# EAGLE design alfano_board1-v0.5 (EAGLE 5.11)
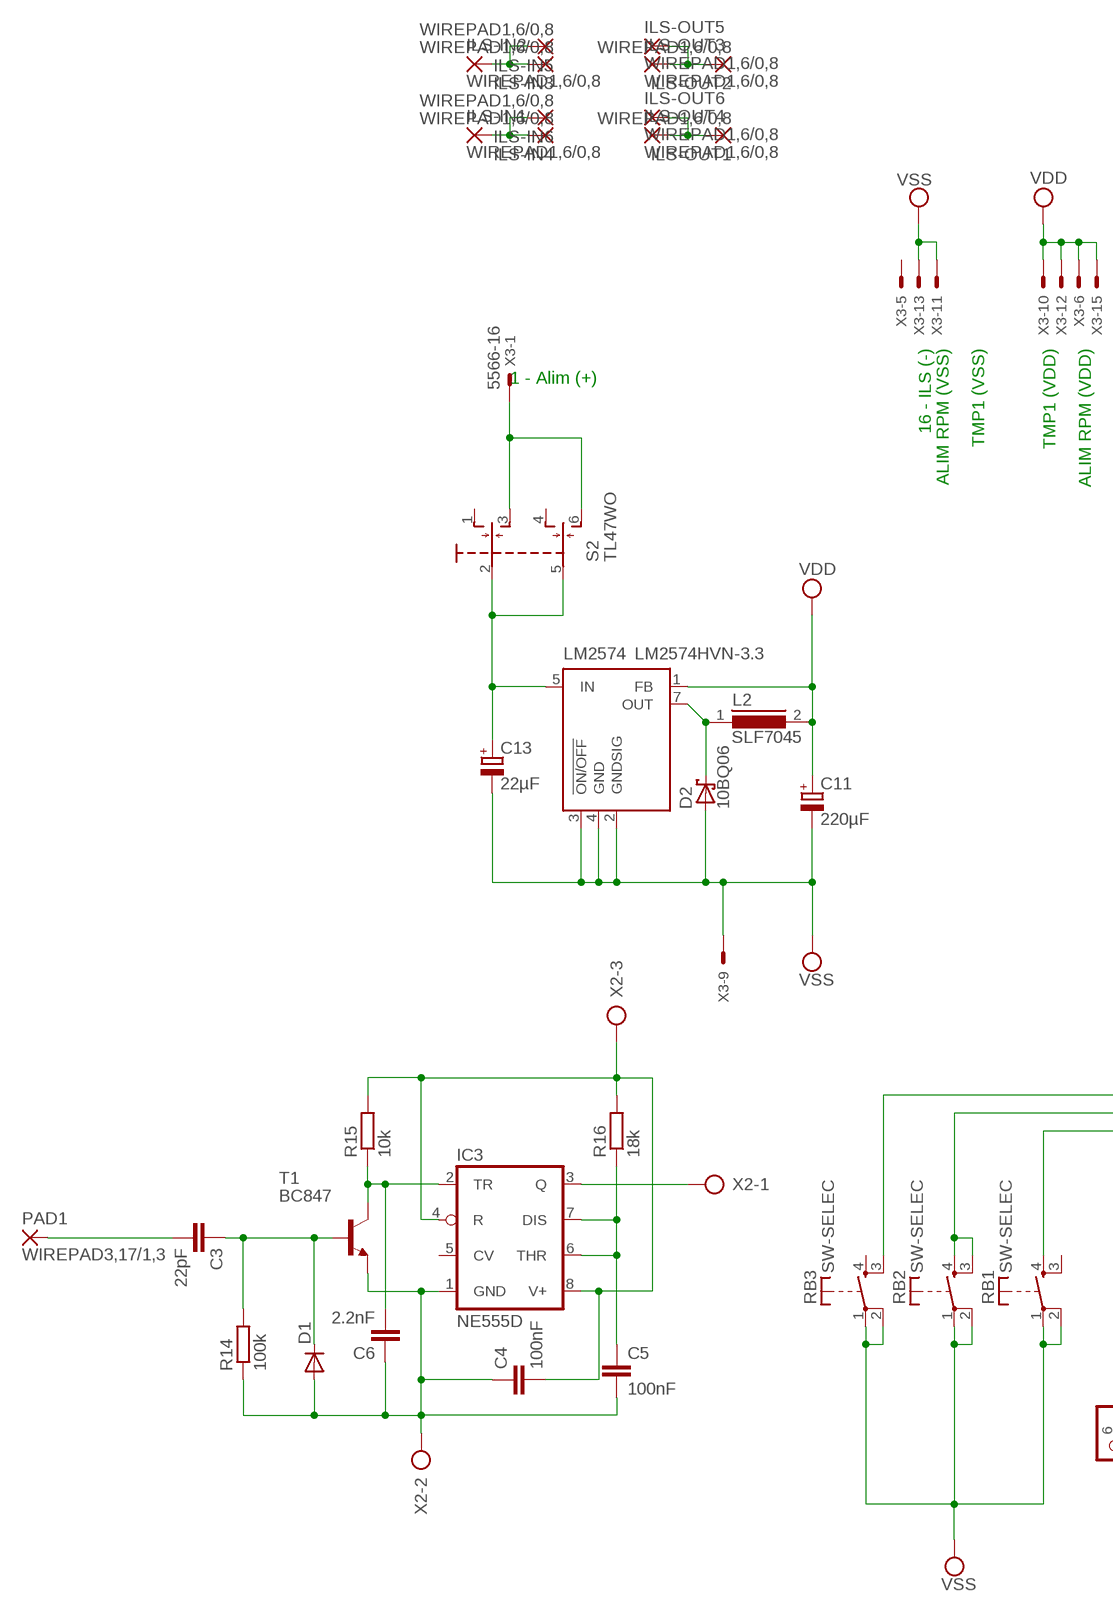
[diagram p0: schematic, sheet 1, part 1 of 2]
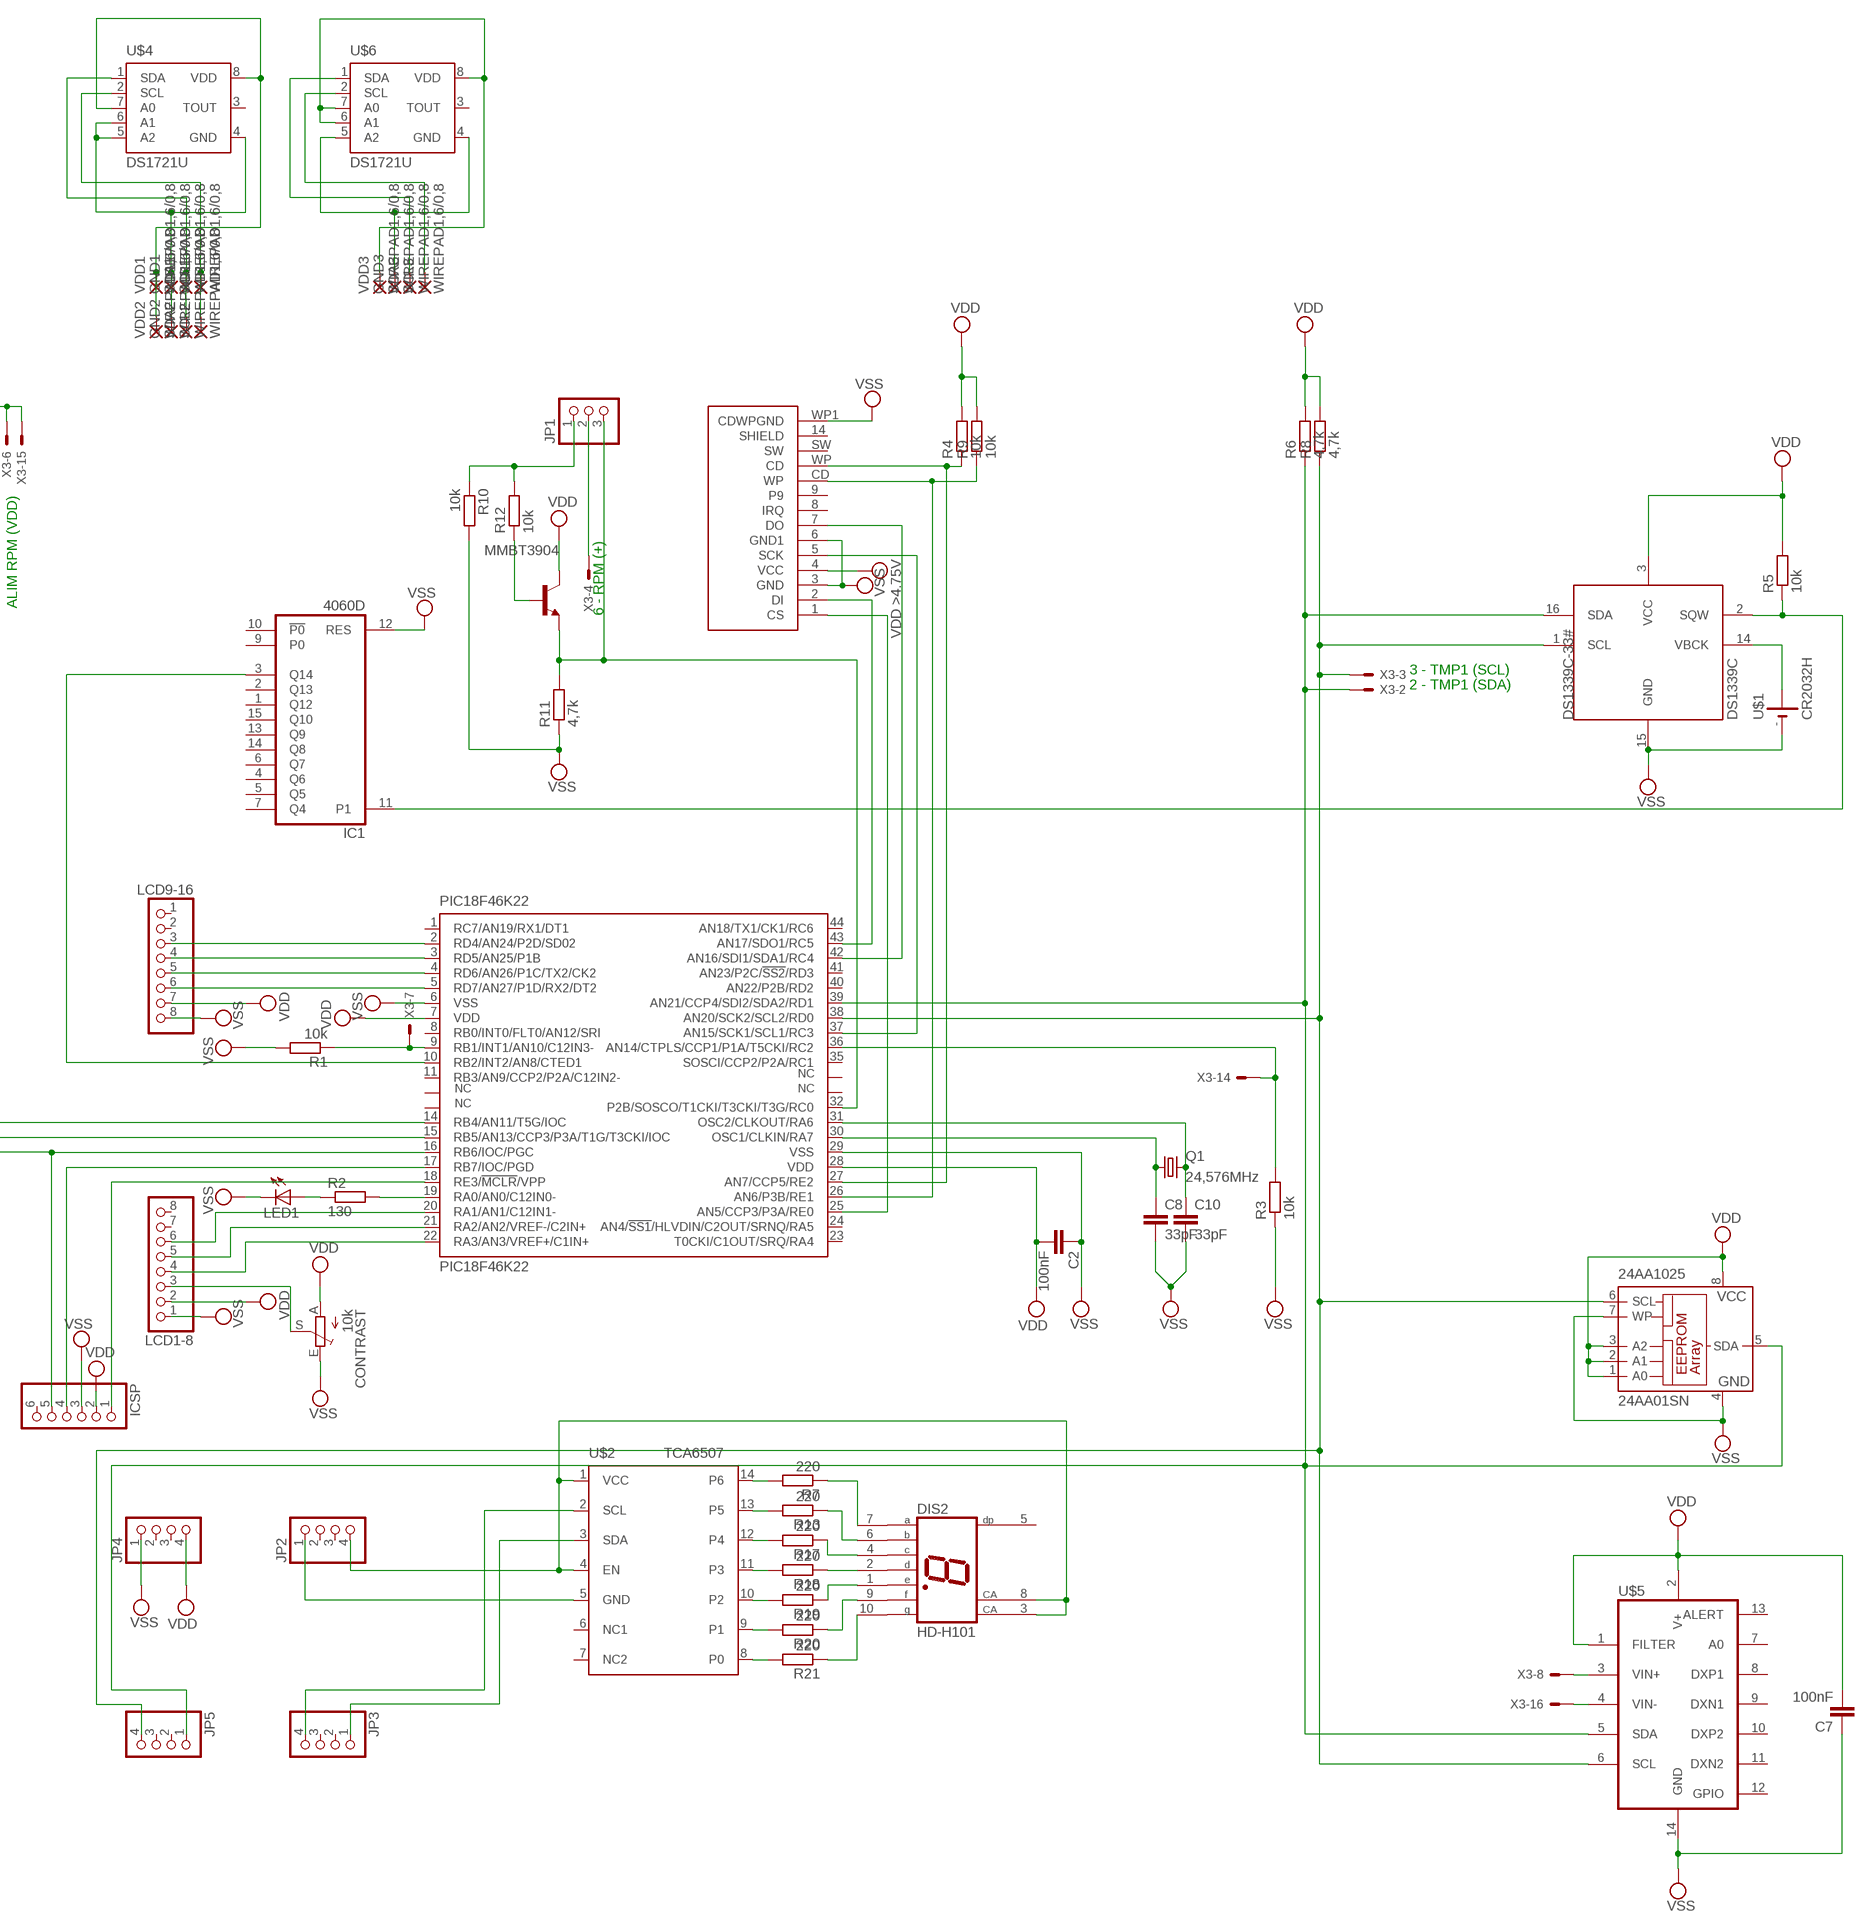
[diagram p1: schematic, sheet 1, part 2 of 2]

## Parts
24AA1025  24AA01SN  [SO-08]
C2  100nF  C-EUC1206  [C1206]
C3  22pF  C-EUC1206  [C1206]
C4  100nF  C-EUC1206  [C1206]
C5  100nF  C-EUC1206  [C1206]
C6  2.2nF  C-EUC1206  [C1206]
C7  100nF  C-EUC1206  [C1206]
C8  33pF  C-EUC1206  [C1206]
C10  33pF  C-EUC1206  [C1206]
C11  220µF  CPOL-EUUD-8X10  [UD-8X10_NICHICON]
C13  22µF  CPOL-EUUD-4X5,8  [UD-4X5,8_NICHICON]
CONTRAST  10k  TRIM_EU-B25P  [B25P]
D1  DIODE-MINIMELF  [MINIMELF]
D2  10BQ06  MBRS130LT3  [SMB]
DIS2  HD-H101  [HDSP-M]
DS1339C-33#  DS1339C  [DS1339C]
GND1  WIREPAD1,6/0,8  [1,6/0,8]
GND2  WIREPAD1,6/0,8  [1,6/0,8]
GND3  WIREPAD1,6/0,8  [1,6/0,8]
IC1  4060D  [SO16]
IC3  NE555D  [SO08]
ICSP  PINHD-1X6  [1X06]
ILS-IN1  WIREPAD1,6/0,8  [1,6/0,8]
ILS-IN2  WIREPAD1,6/0,8  [1,6/0,8]
ILS-IN3  WIREPAD1,6/0,8  [1,6/0,8]
ILS-IN4  WIREPAD1,6/0,8  [1,6/0,8]
ILS-IN5  WIREPAD1,6/0,8  [1,6/0,8]
ILS-IN6  WIREPAD1,6/0,8  [1,6/0,8]
ILS-OUT1  WIREPAD1,6/0,8  [1,6/0,8]
ILS-OUT2  WIREPAD1,6/0,8  [1,6/0,8]
ILS-OUT3  WIREPAD1,6/0,8  [1,6/0,8]
ILS-OUT4  WIREPAD1,6/0,8  [1,6/0,8]
ILS-OUT5  WIREPAD1,6/0,8  [1,6/0,8]
ILS-OUT6  WIREPAD1,6/0,8  [1,6/0,8]
JP1  PINHD-1X3  [1X03]
JP2  PINHD-1X4  [1X04]
JP3  PINHD-1X4  [1X04]
JP4  PINHD-1X4  [1X04]
JP5  PINHD-1X4  [1X04]
L2  SLF7045  [SLF7045]
LCD1-8  PINHD-1X8  [1X08]
LCD9-16  PINHD-1X8  [1X08]
LED1  LED5MM  [LED5MM]
LM2574  LM2574HVN-3.3  [DIL08]
MMBT3904  MMBT3904LT1-NPN-SOT23-BEC  [SOT23-BEC]
PAD1  WIREPAD3,17/1,3  [3,17/1,3]
PIC18F46K22  PIC18F46K22  [TQFP44]
Q1  24,576MHz  CRYSTALHC49U-V  [HC49U-V]
R1  10k  R-EU_M1206  [M1206]
R2  130  R-EU_M1206  [M1206]
R3  10k  R-EU_M1206  [M1206]
R4  10k  R-EU_M1206  [M1206]
R5  10k  R-EU_M1206  [M1206]
R6  4,7k  R-EU_M1206  [M1206]
R7  220  R-EU_M1206  [M1206]
R8  4,7k  R-EU_M1206  [M1206]
R9  10k  R-EU_M1206  [M1206]
R10  10k  R-EU_M1206  [M1206]
R11  4,7k  R-EU_M1206  [M1206]
R12  10k  R-EU_M1206  [M1206]
R13  220  R-EU_M1206  [M1206]
R14  100k  R-EU_M1206  [M1206]
R15  10k  R-EU_M1206  [M1206]
R16  18k  R-EU_M1206  [M1206]
R17  220  R-EU_M1206  [M1206]
R18  220  R-EU_M1206  [M1206]
R19  220  R-EU_M1206  [M1206]
R20  220  R-EU_M1206  [M1206]
R21  220  R-EU_M1206  [M1206]
RB1  SW-SELEC  [SW-SELEC]
RB2  SW-SELEC  [SW-SELEC]
RB3  SW-SELEC  [SW-SELEC]
S2  TL47WO  [TL4XWO]
SCL1  WIREPAD1,6/0,8  [1,6/0,8]
SCL2  WIREPAD1,6/0,8  [1,6/0,8]
SCL3  WIREPAD1,6/0,8  [1,6/0,8]
SDA1  WIREPAD1,6/0,8  [1,6/0,8]
SDA2  WIREPAD1,6/0,8  [1,6/0,8]
SDA3  WIREPAD1,6/0,8  [1,6/0,8]
T1  BC847  [SOT23]
U$1  CR2032H  [CR2032H]
U$2  TCA6507  [TCA6507]
U$3  SD_CARD_SOCKETSD  [SD-MMC_SOCKET-PP]
U$4  DS1721U  [UMAX-8PIN]
U$5  TMP512  [TMP512]
U$6  DS1721U  [UMAX-8PIN]
VDD1  WIREPAD1,6/0,8  [1,6/0,8]
VDD2  WIREPAD1,6/0,8  [1,6/0,8]
VDD3  WIREPAD1,6/0,8  [1,6/0,8]
X2  AK500/3  [AK500/3]
X3  5566-16  [5566-16]

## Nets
N$1: 24AA1025.6(SCL) DS1339C-33#.1(SCL) JP5.4 PIC18F46K22.38(AN20/SCK2/SCL2/RD0) R8.1 U$5.6(SCL) X3.3
N$2: PIC18F46K22.9(RB1/INT1/AN10/C12IN3-) R1.1 X3.7
N$3: PIC18F46K22.19(RA0/AN0/C12IN0-) R2.2
N$4: LCD1-8.6 PIC18F46K22.20(RA1/AN1/C12IN1-)
N$5: LCD1-8.4 PIC18F46K22.22(RA3/AN3/VREF+/C1IN+)
N$6: LCD9-16.5 PIC18F46K22.4(RD6/AN26/P1C/TX2/CK2)
N$7: LED1.A R2.1
N$8: ICSP.5 PIC18F46K22.16(RB6/IOC/PGC) RB1.4(S)
N$9: PIC18F46K22.42(AN16/SDI1/SDA1/RC4) U$3.7(DO)
N$10: PIC18F46K22.43(AN17/SDO1/RC5) U$3.2(DI)
N$11: C13.+ LM2574.5(IN) S2.2(P) S2.5(P1)
N$12: DS1339C-33#.14(VBCK) U$1.+@1(+)
N$14: LCD9-16.3 PIC18F46K22.2(RD4/AN24/P2D/SD02)
N$16: PIC18F46K22.25(AN5/CCP3/P3A/RE0) U$3.1(CS)
N$17: C3.1 D1.C R14.2 T1.1(B)
N$18: PIC18F46K22.26(AN6/P3B/RE1) R9.1 U$3.CD(WP)
N$19: PIC18F46K22.37(AN15/SCK1/SCL1/RC3) U$3.5(SCK)
N$20: ICSP.1 PIC18F46K22.18(RE3/!MCLR!/VPP)
N$21: PIC18F46K22.27(AN7/CCP5/RE2) R4.1 U$3.WP(CD)
N$22: C8.1 PIC18F46K22.30(OSC1/CLKIN/RA7) Q1.1
N$23: DS1339C-33#.2(SQW) IC1.11(P1) R5.1
N$24: ICSP.4 PIC18F46K22.17(RB7/IOC/PGD)
N$25: SCL1.1(P) SCL2.1(P) U$4.2(SCL)
N$26: LCD9-16.4 PIC18F46K22.3(RD5/AN25/P1B)
N$27: SDA1.1(P) SDA2.1(P) U$4.1(SDA)
N$28: GND1.1(P) GND2.1(P) U$4.4(GND) U$4.5(A2) U$4.6(A1)
N$29: LCD1-8.5 PIC18F46K22.21(RA2/AN2/VREF-/C2IN+)
N$30: PIC18F46K22.36(AN14/CTPLS/CCP1/P1A/T5CKI/RC2) R3.2 X3.14
N$31: PIC18F46K22.14(RB4/AN11/T5G/IOC) RB3.3(S)
N$32: PIC18F46K22.15(RB5/AN13/CCP3/P3A/T1G/T3CKI/IOC) RB2.3(S) RB2.4(S)
N$33: S2.3(S) S2.6(S1) X3.1
N$34: CONTRAST.S LCD1-8.3
N$35: 24AA1025.5(SDA) DS1339C-33#.16(SDA) JP5.1 PIC18F46K22.39(AN21/CCP4/SDI2/SDA2/RD1) R6.1 U$5.5(SDA) X3.2
N$36: IC1.3(Q14) PIC18F46K22.10(RB2/INT2/AN8/CTED1)
N$37: D2.C L2.1 LM2574.7(OUT)
N$38: LCD9-16.6 PIC18F46K22.5(RD7/AN27/P1D/RX2/DT2)
N$39: U$4.7(A0) U$4.8(VDD) VDD1.1(P) VDD2.1(P)
N$42: C10.1 PIC18F46K22.31(OSC2/CLKOUT/RA6) Q1.2
N$44: JP1.2 X3.4
N$45: MMBT3904.B R12.1
N$46: U$6.6(A1) U$6.7(A0) U$6.8(VDD) VDD3.1(P)
N$47: JP1.3 MMBT3904.E PIC18F46K22.32(P2B/SOSCO/T1CKI/T3CKI/T3G/RC0) R11.2
N$48: GND3.1(P) U$6.4(GND) U$6.5(A2)
N$49: SDA3.1(P) U$6.1(SDA)
N$50: SCL3.1(P) U$6.2(SCL)
N$52: C5.1 IC3.6(THR) IC3.7(DIS) R16.1
N$53: JP1.1 R10.1 R12.2
N$54: ILS-IN2.1(P) ILS-IN3.1(P) ILS-IN5.1(P)
N$55: ILS-IN1.1(P) ILS-IN4.1(P) ILS-IN6.1(P)
N$56: ILS-OUT1.1(P) ILS-OUT4.1(P) ILS-OUT6.1(P)
N$57: ILS-OUT2.1(P) ILS-OUT3.1(P) ILS-OUT5.1(P)
N$58: IC3.3(Q) X2.1
N$59: C6.2 IC3.2(TR) R15.1 T1.3(C)
N$60: C3.2 PAD1.1(P)
N$61: C4.2 IC3.4(R) IC3.8(V+) R15.2 R16.2 X2.3
N$62: DIS2.7(A) R7.1
N$64: DIS2.6(B) R13.1
N$65: DIS2.4(C) R17.1
N$66: R7.2 U$2.14(P6)
N$67: DIS2.1(E) R19.1
N$68: DIS2.9(F) R20.1
N$69: DIS2.10(G) R21.1
N$70: U$5.4(VIN-) X3.16
N$71: DIS2.3(CA) DIS2.8(CA) JP2.4 U$2.1(VCC) U$2.4(EN)
N$72: R13.2 U$2.13(P5)
N$73: R17.2 U$2.12(P4)
N$74: R18.2 U$2.11(P3)
N$75: R19.2 U$2.10(P2)
N$76: R20.2 U$2.9(P1)
N$77: R21.2 U$2.8(P0)
N$78: DIS2.2(D) R18.1
N$79: JP2.1 U$2.5(GND)
N$80: JP3.1 U$2.3(SDA)
N$81: JP3.4 U$2.2(SCL)
N$82: U$5.3(VIN+) X3.8
VDD: 24AA1025.1(A0) 24AA1025.2(A1) 24AA1025.3(A2) 24AA1025.8(VCC) C2.2 C7.2 C11.+ CONTRAST.A DS1339C-33#.3(VCC) ICSP.2 JP4.4 L2.2 LCD1-8.2 LCD9-16.7 LM2574.1(FB) MMBT3904.C PIC18F46K22.7(VDD) PIC18F46K22.28(VDD) R4.2 R5.2 R6.2 R8.2 R9.2 U$3.4(VCC) U$5.1(FILTER) U$5.2(V+) X3.6 X3.10 X3.12 X3.15 ; supply symbol labelled VDD >4.75V
VSS: 24AA1025.4(GND) 24AA1025.7(WP) C2.1 C7.1 C8.2 C10.2 C11.- C13.- CONTRAST.E D2.A DS1339C-33#.15(GND) IC1.12(RES) ICSP.3 JP4.1 LCD1-8.1 LCD9-16.8 LED1.K(C) LM2574.2(GNDSIG) LM2574.3(!ON/OFF) LM2574.4(GND) PIC18F46K22.6(VSS) PIC18F46K22.29(VSS) R1.2 R3.1 R10.2 R11.1 RB1.1(P) RB1.2(P) RB2.1(P) RB2.2(P) RB3.1(P) RB3.2(P) U$1.- U$3.3(GND) U$3.6(GND1) U$3.WP1(CDWPGND) U$5.14(GND) X3.9 X3.11 X3.13
VSS2: C4.1 C5.2 C6.1 D1.A IC3.1(GND) R14.1 T1.2(E) X2.2
Unconnected: DIS2.5(DP) IC1.1(Q12) IC1.2(Q13) IC1.4(Q6) IC1.5(Q5) IC1.6(Q7) IC1.7(Q4) IC1.9(P0) IC1.10(!P0) IC1.13(Q9) IC1.14(Q8) IC1.15(Q10) IC3.5(CV) ICSP.6 JP2.2 JP2.3 JP3.2 JP3.3 JP4.2 JP4.3 JP5.2 JP5.3 LCD1-8.7 LCD1-8.8 LCD9-16.1 LCD9-16.2 PIC18F46K22.1(RC7/AN19/RX1/DT1) PIC18F46K22.8(RB0/INT0/FLT0/AN12/SRI) PIC18F46K22.11(RB3/AN9/CCP2/P2A/C12IN2-) PIC18F46K22.12(NC) PIC18F46K22.13(NC.) PIC18F46K22.23(T0CKI/C1OUT/SRQ/RA4) PIC18F46K22.24(AN4/!SS1!/HLVDIN/C2OUT/SRNQ/RA5) PIC18F46K22.33(N.C.) PIC18F46K22.34(NC..) PIC18F46K22.35(SOSCI/CCP2/P2A/RC1) PIC18F46K22.40(AN22/P2B/RD2) PIC18F46K22.41(AN23/P2C/!SS2!/RD3) PIC18F46K22.44(AN18/TX1/CK1/RC6) RB1.3(S) RB3.4(S) S2.1(O) S2.4(O1) U$2.6(NC1) U$2.7(NC2) U$3.8(IRQ) U$3.9 U$3.14(SHIELD) U$3.SW U$4.3(TOUT) U$5.7(A0) U$5.8(DXP1) U$5.9(DXN1) U$5.10(DXP2) U$5.11(DXN2) U$5.12(GPIO) U$5.13(ALERT) U$6.3(TOUT) X3.5

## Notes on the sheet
- 16 - ILS (-) | ALIM RPM (VSS) | TMP1 (VSS) | TMP1 (VDD) | ALIM RPM (VDD)
- 1 - Alim (+)
- 6 - RPM (+)
- 3 - TMP1 (SCL)
- 2 - TMP1 (SDA)

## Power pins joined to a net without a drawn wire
VDD: IC1.16(VDD)
VSS: IC1.8(VSS)

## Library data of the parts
24AA1025 = microchip:24*: Serial EEPROM I2C; MF: MICROCHIP; MPN: 24AA01/SN; OC_FARNELL: 1331268; OC_NEWARK: 89C9792
C2-C8 C10 = rcl:C-EU: CAPACITOR, European symbol
C11 C13 = rcl:CPOL-EU: POLARIZED CAPACITOR, European symbol
CONTRAST = pot:TRIM_EU-: POTENTIOMETER
D1 = diode:DIODE-: DIODE
D2 = diode_corr:MBRS130LT3: Schottky Power Rectifier
DIS2 = display-hp:HD-H101: LED DISPLAY 1-character 7 segment, decimal point right; OC_FARNELL: unknown; OC_NEWARK: unknown
DS1339C-33# = maxim-1339C:DS1339C: Real-Time Clock (RTC) Counts Seconds, Minutes, Hours, Day, Date, Month, and Year with Leap-Year Compensation Valid Up to 2100
GND1-GND3 ILS-IN1-ILS-IN6 ILS-OUT1-ILS-OUT6 PAD1 SCL1-SCL3 SDA1-SDA3 VDD1-VDD3 = wirepad:WIREPAD: Wire PAD connect wire on PCB
IC1 = 40xx:4060: 14-stage binary/ripple COUNTER
IC3 = linear:*555: TIMER
ICSP = pinhead:PINHD-1X6: PIN HEADER
JP1 = pinhead:PINHD-1X3: PIN HEADER
JP2-JP5 = pinhead:PINHD-1X4: PIN HEADER
L2 = inductors:SLF7045: SMD Inductors(Coils) For Power Line (Wound, Magnetic Shielded)
LCD1-8 LCD9-16 = pinhead:PINHD-1X8: PIN HEADER
LED1 = led:LED: LED
LM2574 = linear:LM2574?-*: SIMPLE SWITCHER 0.5A Step-Down Voltage Regulator Source: http://cache.national.com/ds/LM/LM2574.pdf
MMBT3904 = transistor:*-NPN-: NPN Transistror BF959 corrected 2008.03.06
PIC18F46K22 = microchip_KM2:PIC18F46K22
Q1 = crystal:CRYSTAL: CRYSTAL; OC_FARNELL: 1666969; OC_NEWARK: unknown
R1-R21 = rcl:R-EU_: RESISTOR, European symbol
RB1-RB3 = maxim-1339C:SW-SELEC
S2 = switch_epi:TL47WO: TINY SWITCH MOM OFF MOM Source: http://www2.produktinfo.conrad.com/datenblaetter/700000-724999/705152-da-01-de-Subminiaturschalter_TL_36WO.pdf
T1 = transistor:BC847: NPN TRANSISTOR
U$1 = maxim-1339C:CR2032H
U$2 = picfano:TCA6507
U$3 = SparkFun_epi:SD_CARD_SOCKET: SD/MMC Socket Media socket for SD and MMC cards. Push-push type. Schematic element and footprint production proven. Spark Fun Electronics SKU : PRT-00136
U$4 U$6 = picfano:DS1721U
U$5 = picfano:TMP512
X2 = con-ptr500:AK500/3: CONNECTOR; OC_FARNELL: unknown; OC_NEWARK: unknown
X3 = con-molex:5566-16: Mini FIT connector 16 pol Source: http://www.molex.com; OC_FARNELL: unknown; OC_NEWARK: unknown

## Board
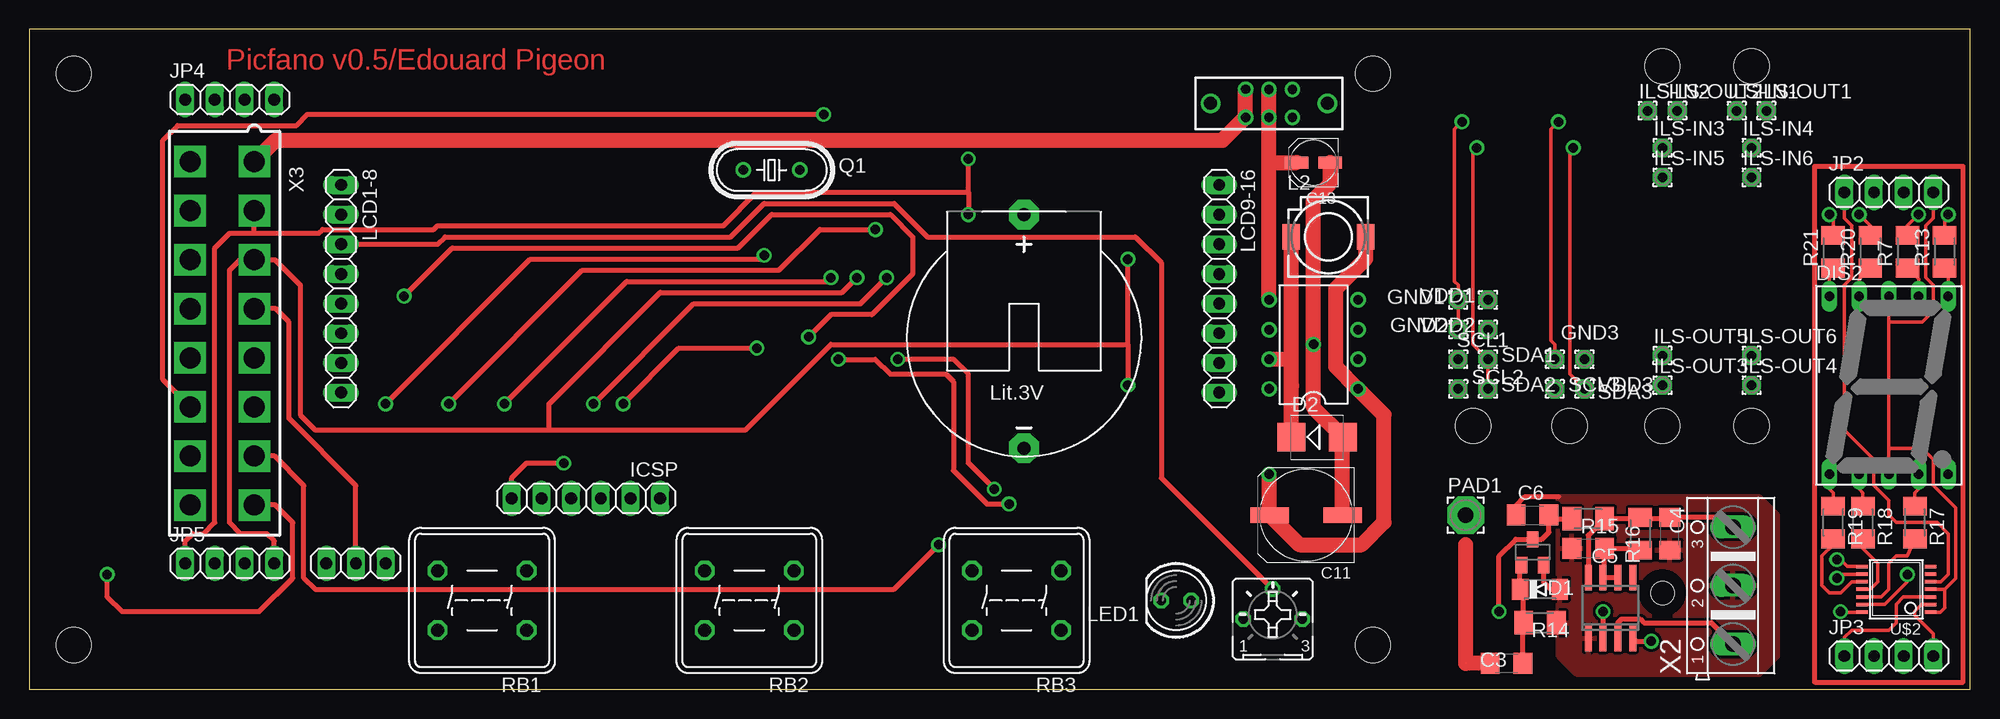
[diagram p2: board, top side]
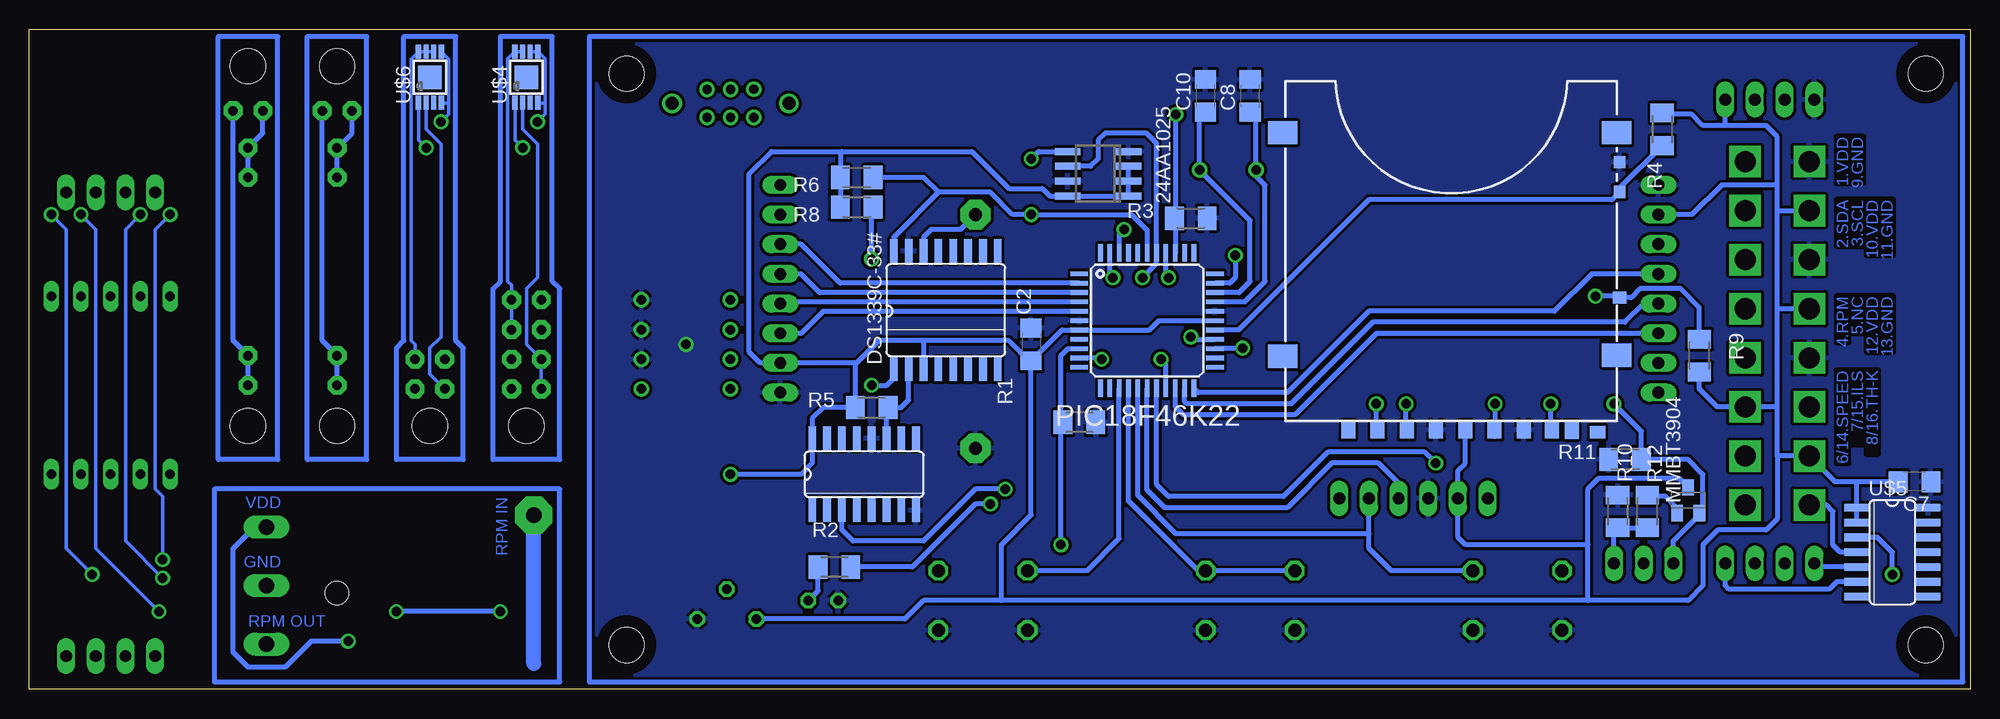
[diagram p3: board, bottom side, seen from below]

Size 166.03 x 56.5 mm. Coordinates in mm from the lower left corner, seen from the top.
Outline: 0,0 166.03,0 166.03,56.5 0,56.5 0,0
Copper layers (1*16): Top 0.035mm / dielectric 1.5mm / Bottom 0.035mm
Design rules "10mils": minimum track width 10mil, minimum drill 24mil, track to track 10mil, track to pad 10mil, pad to pad 10mil, via to via 10mil, smd to smd 10mil, copper to edge 40mil, drill to drill 10mil, minimum pad ring 10mil, minimum via ring 8mil, stop-mask expansion 0mil, vias tented up to drill 0mil, thermal gap 10mil
Holes 3 mm at 3.81,52.7 3.81,3.81 114.94,3.81 114.94,52.7 139.7,22.54 139.7,53.34 147.32,53.34 147.32,22.54 123.51,22.54 131.76,22.54
Holes 2 mm at 139.7,8.25

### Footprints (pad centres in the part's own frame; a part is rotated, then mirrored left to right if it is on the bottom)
SO-08 = smd 0.6 x 2.2: 1 -1.905,-2.6; 2 -0.635,-2.6; 3 0.635,-2.6; 4 1.905,-2.6; 5 1.905,2.6; 6 0.635,2.6; 7 -0.635,2.6; 8 -1.905,2.6
C1206 = smd 1.6 x 1.8: 1 -1.4,0; 2 1.4,0
UD-8X10_NICHICON = smd 3.3 x 1.3: + 3.125,0; - -3.125,0
UD-4X5,8_NICHICON = smd 2 x 1: + 1.425,0; - -1.425,0
B25P = drill 0.813 octagon: A -2.54,0; E 2.54,0; S 0,2.54
MINIMELF = smd 1.4 x 1.8: A 1.7,0; C -1.7,0
SMB = smd 2.4 x 2.4: A 2.2,0; C -2.2,0
HDSP-M = drill 0.813 long: 1 -5.08,-7.62; 2 -2.54,-7.62; 3 0,-7.62; 4 2.54,-7.62; 5 5.08,-7.62; 6 5.08,7.62; 7 2.54,7.62; 8 0,7.62; 9 -2.54,7.62; 10 -5.08,7.62
DS1339C = smd 0.66 x 2.032: 1 -4.445,-4.978; 2 -3.175,-4.978; 3 -1.905,-4.978; 4 -0.635,-4.978; 5 0.635,-4.978; 6 1.905,-4.978; 7 3.175,-4.978; 8 4.445,-4.978; 9 4.445,5.137; 10 3.175,5.137; 11 1.905,5.137; 12 0.635,5.137; 13 -0.635,5.137; 14 -1.905,5.137; 15 -3.175,5.137; 16 -4.445,5.137
1,6/0,8 = drill 0.813 pad 1.6 octagon: 1 0,0
SO16 = smd 0.66 x 2.032: 1 -4.445,-3.073; 2 -3.175,-3.073; 3 -1.905,-3.073; 4 -0.635,-3.073; 5 0.635,-3.073; 6 1.905,-3.073; 7 3.175,-3.073; 8 4.445,-3.073; 9 4.445,3.073; 10 3.175,3.073; 11 1.905,3.073; 12 0.635,3.073; 13 -0.635,3.073; 14 -1.905,3.073; 15 -3.175,3.073; 16 -4.445,3.073
SO08 = smd 0.6 x 2.2: 1 -1.905,-2.6; 2 -0.635,-2.6; 3 0.635,-2.6; 4 1.905,-2.6; 5 1.905,2.6; 6 0.635,2.6; 7 -0.635,2.6; 8 -1.905,2.6
1X06 = drill 1.016 long: 1 -6.35,0; 2 -3.81,0; 3 -1.27,0; 4 1.27,0; 5 3.81,0; 6 6.35,0
1X03 = drill 1.016 long: 1 -2.54,0; 2 0,0; 3 2.54,0
1X04 = drill 1.016 long: 1 -3.81,0; 2 -1.27,0; 3 1.27,0; 4 3.81,0
SLF7045 = smd 1.5 x 2.2: 1 -3.2,0; 2 3.2,0
1X08 = drill 1.016 long: 1 -8.89,0; 2 -6.35,0; 3 -3.81,0; 4 -1.27,0; 5 1.27,0; 6 3.81,0; 7 6.35,0; 8 8.89,0
LED5MM = drill 0.813 octagon: A -1.27,0; K 1.27,0
DIL08 = drill 0.813 pad 1.27 round: 1 -3.81,-3.81; 2 -1.27,-3.81; 3 1.27,-3.81; 4 3.81,-3.81; 5 3.81,3.81; 6 1.27,3.81; 7 -1.27,3.81; 8 -3.81,3.81
SOT23-BEC = smd 1 x 1.4: B -0.95,-1.1; C 0,1.1; E 0.95,-1.1
3,17/1,3 = drill 1.321 pad 3.175 octagon: 1 0,0
TQFP44 = smd 1.5 x 0.4: 1 -5.8,4; 2 -5.8,3.2; 3 -5.8,2.4; 4 -5.8,1.6; 5 -5.8,0.8; 6 -5.8,0; 7 -5.8,-0.8; 8 -5.8,-1.6; 9 -5.8,-2.4; 10 -5.8,-3.2; 11 -5.8,-4; 23 5.8,-4; 24 5.8,-3.2; 25 5.8,-2.4; 26 5.8,-1.6; 27 5.8,-0.8; 28 5.8,0; 29 5.8,0.8; 30 5.8,1.6; 31 5.8,2.4; 32 5.8,3.2; 33 5.8,4 | smd 0.4 x 1.5: 12 -4,-5.8; 13 -3.2,-5.8; 14 -2.4,-5.8; 15 -1.6,-5.8; 16 -0.8,-5.8; 17 0,-5.8; 18 0.8,-5.8; 19 1.6,-5.8; 20 2.4,-5.8; 21 3.2,-5.8; 22 4,-5.8; 34 4,5.8; 35 3.2,5.8; 36 2.4,5.8; 37 1.6,5.8; 38 0.8,5.8; 39 0,5.8; 40 -0.8,5.8; 41 -1.6,5.8; 42 -2.4,5.8; 43 -3.2,5.8; 44 -4,5.8
HC49U-V = drill 0.813 round: 1 -2.413,0; 2 2.413,0
M1206 = smd 1.6 x 2: 1 -1.4,0; 2 1.4,0
SW-SELEC = drill 1.118 octagon: 1 -3.81,2.54; 2 3.81,2.54; 3 3.81,-2.54; 4 -3.81,-2.54
TL4XWO = drill 0.8 pad 1.27 round: 1 -2,1.2; 2 0,1.2; 3 2,1.2; 4 -2,-1.195; 5 0,-1.195; 6 2,-1.205 | drill 1.1 pad 1.676 round: M3 -5,0; M4 5,0
SOT23 = smd 1 x 1.4: 1 -0.95,-1.1; 2 0.95,-1.1; 3 0,1.1
CR2032H = drill 1.118 pad 2.54 octagon: +@1 0,10.795; - 0,-9.207
TCA6507 = smd 0.305 x 0.991: 1 -1.95,-2.918; 2 -1.3,-2.918; 3 -0.65,-2.918; 4 0,-2.918; 5 0.65,-2.918; 6 1.3,-2.918; 7 1.95,-2.918; 8 1.95,2.918; 9 1.3,2.918; 10 0.65,2.918; 11 0,2.918; 12 -0.65,2.918; 13 -1.3,2.918; 14 -1.95,2.918
SD-MMC_SOCKET-PP = smd 1.2 x 1.5: 1 6.88,29.85; 2 4.38,29.85; 3 1.88,29.85; 4 -0.62,29.85; 5 -3.12,29.85; 6 -5.62,29.85; 7 -8.04,29.85; 8 -9.728,29.87; 9 9.38,29.85 | smd 2.5 x 2: 10 -13.57,4.415; 11 15.005,4.415; 14 -13.57,23.465; 15 15.005,23.555 | smd 1.15 x 1: CD -13.815,18.53 | smd 1.3 x 1.1: SW -11.938,30.048 | smd 1 x 1.05: WP -13.815,9.482; WP1 -13.815,6.942
UMAX-8PIN = smd 0.45 x 1.2: 1 -0.975,-2.175; 2 -0.325,-2.175; 3 0.325,-2.175; 4 0.975,-2.175; 5 0.975,2.175; 6 0.325,2.175; 7 -0.325,2.175; 8 -0.975,2.175 | smd 2 x 2: TH 0,0
TMP512 = smd 0.66 x 2.032: 1 -4.445,-3.073; 2 -3.175,-3.073; 3 -1.905,-3.073; 4 -0.635,-3.073; 5 0.635,-3.073; 6 1.905,-3.073; 7 3.175,-3.073; 8 3.175,3.073; 9 1.905,3.073; 10 0.635,3.073; 11 -0.635,3.073; 12 -1.905,3.073; 13 -3.175,3.073; 14 -4.445,3.073
AK500/3 = drill 1.321 long: 1 -5.004,0; 2 0,0; 3 5.004,0
5566-16 = drill 1.8 square: 1 14.7,-2.75; 2 10.5,-2.75; 3 6.3,-2.75; 4 2.1,-2.75; 5 -2.1,-2.75; 6 -6.3,-2.75; 7 -10.5,-2.75; 8 -14.7,-2.75; 9 14.7,2.75; 10 10.5,2.75; 11 6.3,2.75; 12 2.1,2.75; 13 -2.1,2.75; 14 -6.3,2.75; 15 -10.5,2.75; 16 -14.7,2.75

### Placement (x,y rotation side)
24AA1025  74.61,44.13 90 bottom
C2  80.33,29.53 270 bottom
C3  126.37,2.22 180 top
C4  140.34,13.34 90 top
C5  133.35,12.06 180 top
C6  128.59,14.92 0 top
C7  4.76,17.78 180 bottom
C8  61.59,50.8 90 bottom
C10  65.41,50.8 90 bottom
C11  109.22,14.92 180 top
C13  109.86,45.09 180 top
CONTRAST  106.36,6.03 0 top
D1  129.22,8.57 0 top
D2  110.17,21.59 0 top
DIS2  159.07,26.04 0 top
DS1339C-33#  87.63,32.38 0 bottom
GND1  122.24,33.34 270 top
GND2  122.24,30.8 0 top
GND3  130.49,28.26 270 top
IC1  94.62,18.41 0 bottom
IC3  135.25,6.98 0 top
ICSP  47.62,16.35 0 top
ILS-IN1  146.05,49.53 0 top
ILS-IN2  138.43,49.53 0 top
ILS-IN3  139.7,46.35 0 top
ILS-IN4  147.32,46.35 0 top
ILS-IN5  139.7,43.82 0 top
ILS-IN6  147.32,43.82 0 top
ILS-OUT1  148.59,49.53 0 top
ILS-OUT2  140.97,49.53 0 top
ILS-OUT3  139.7,26.04 0 top
ILS-OUT4  147.32,26.04 0 top
ILS-OUT5  139.7,28.57 0 top
ILS-OUT6  147.32,28.57 0 top
JP1  27.94,10.79 180 top
JP2  159.07,42.54 0 top
JP3  159.07,2.86 0 top
JP4  17.15,50.48 0 top
JP5  17.15,10.79 0 top
L2  111.12,38.73 0 top
LCD1-8  26.67,34.29 270 top
LCD9-16  101.79,34.29 270 top
LED1  98.11,7.62 180 top
LM2574  109.86,29.53 90 top
MMBT3904  24.13,16.19 0 bottom
PAD1  122.87,14.92 0 top
PIC18F46K22  70.41,31.56 0 bottom
Q1  63.5,44.45 0 top
R1  76.2,22.86 0 bottom
R2  97.16,10.48 0 bottom
R3  66.67,40.32 180 bottom
R4  26.35,47.94 90 bottom
R5  93.98,24.13 180 bottom
R6  95.25,43.82 180 bottom
R7  160.66,37.46 90 top
R8  95.25,41.27 180 bottom
R9  23.18,28.57 270 bottom
R10  30.16,15.24 90 bottom
R11  29.53,19.68 0 bottom
R12  27.62,15.24 270 bottom
R13  163.83,37.46 90 top
R14  129.22,5.71 180 top
R15  133.35,14.6 0 top
R16  137.79,13.34 90 top
R17  161.29,14.29 270 top
R18  156.84,14.29 270 top
R19  154.31,14.29 270 top
R20  157.48,37.46 90 top
R21  154.31,37.46 90 top
RB1  38.73,7.62 180 top
RB2  61.59,7.62 180 top
RB3  84.45,7.62 180 top
S2  106.05,50.16 180 top
SCL1  122.24,28.26 270 top
SCL2  122.24,25.72 0 top
SCL3  130.49,25.72 270 top
SDA1  124.78,28.26 270 top
SDA2  124.78,25.72 0 top
SDA3  133.03,25.72 270 top
T1  128.59,11.75 0 top
U$1  85.09,29.84 0 top
U$2  159.7,8.57 90 top
U$3  43.81,52.07 180 bottom
U$4  123.51,52.39 0 bottom
U$5  6.67,11.11 270 bottom
U$6  131.76,52.39 0 bottom
VDD1  124.78,33.34 270 top
VDD2  124.78,30.8 0 top
VDD3  133.03,28.26 270 top
X2  145.73,8.89 90 top
X3  16.51,30.48 90 top

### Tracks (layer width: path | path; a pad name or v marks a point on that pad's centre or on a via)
N$1  (via drill 0.81 pad 1.27)
  Top 0.406: 93.98,29.53 v93.98,26.04 | 93.98,29.53 v93.98,36.83 | 44.45,22.23 24.45,22.23 23.18,23.49 23.18,34.61 21.01,36.78 X3.3 18.05,36.78 17.15,35.88 17.15,14.29 18.1,13.34 20.32,13.34 20.96,12.7 JP5.4 | v70.8,35.24 69.53,33.97 53.98,33.97 44.45,24.45 44.45,22.23 | 44.45,22.23 61.28,22.23 68.58,29.53 93.98,29.53
  Bottom 0.406: DS1339C-33#.1 92.08,26.67 92.71,26.04 v93.98,26.04 | 24AA1025.6 75.25,44.77 74.61,45.4 74.61,46.99 73.98,47.62 70.48,47.62 69.61,46.75 PIC18F46K22.38 69.61,36.44 v70.8,35.24 | U$5.6 11.43,9.21 12.07,8.57 20.64,8.57 20.96,8.89 JP5.4 | v93.98,36.83 93.98,41.15 R8.1
N$2  (via drill 0.81 pad 1.27)
  Top 0.406: v77.79,12.38 73.98,8.57 24.45,8.57 23.5,9.52 23.5,17.46 20.98,19.98 X3.7
  Bottom 0.406: PIC18F46K22.9 77.2,29.16 77.79,28.57 77.79,22.86 | v77.79,12.38 77.79,22.86 | 77.79,22.86 R1.1
N$3  (via drill 0.81 pad 1.27)
  Top 0.406: v69.22,28.26 72.39,28.26 73.66,26.99 78.42,26.99 79.06,26.35 79.06,18.73 81.92,15.88 v83.82,15.88
  Bottom 0.406: v83.82,15.88 85.09,15.88 90.49,10.48 R2.2 | PIC18F46K22.19 68.81,27.85 v69.22,28.26
N$4
  Bottom 0.406: LCD1-8.6 50.8,30.48 57.78,23.49 67.31,23.49 68.01,24.19 PIC18F46K22.20
N$5
  Bottom 0.406: LCD1-8.4 32.39,35.56 35.56,32.38 51.44,32.38 58.42,25.4 66.04,25.4 PIC18F46K22.22
N$6
  Bottom 0.406: PIC18F46K22.4 101.65,33.16 LCD9-16.5
N$7
  Bottom 0.406: R2.1 98.56,8.44 LED1.A
N$8
  Bottom 0.406: PIC18F46K22.16 71.21,16.6 67.95,13.34 51.44,13.34 | 51.44,13.34 51.44,12.06 49.53,10.16 RB1.4 | 51.44,13.34 ICSP.5
N$9  (via drill 0.81 pad 1.27)
  Top 0.406: v72.39,39.37 67.63,39.37 64.14,35.88 47.31,35.88 v35.88,24.45
  Bottom 0.406: PIC18F46K22.42 72.81,38.95 v72.39,39.37 | v35.88,24.45 35.88,22.32 U$3.7
N$10  (via drill 0.81 pad 1.27)
  Top 0.406: v73.34,35.24 71.12,33.02 56.83,33.02 v48.26,24.45
  Bottom 0.406: v48.26,24.45 48.26,22.29 U$3.2 | PIC18F46K22.43 73.61,35.51 v73.34,35.24
N$11
  Top 1.27: S2.5 S2.2 106.05,45.09 | LM2574.5 106.05,45.09 | 106.05,45.09 C13.+
N$12
  Bottom 0.406: DS1339C-33#.14 89.54,38.73 88.9,39.37 86.36,39.37 U$1.+@1
N$13
  Top 0.406: 152.72,44.77 165.42,44.77 165.42,0.63 152.72,0.63 152.72,44.77
N$14
  Bottom 0.406: PIC18F46K22.2 96.68,34.76 100.01,38.1 LCD9-16.3
N$15
  Bottom 0.406: 0.64,55.88 118.11,55.88 118.11,0.63 0.64,0.63 0.64,55.88
N$16  (via drill 0.81 pad 1.27)
  Top 0.406: v50.8,24.45 55.56,29.21 v62.23,29.21
  Bottom 0.406: v50.8,24.45 50.8,22.32 U$3.1 | PIC18F46K22.25 62.28,29.16 v62.23,29.21
N$17
  Top 0.406: C3.1 127.77,5.66 R14.2 127.82,8.27 D1.C 127.52,10.53 T1.1
N$18  (via drill 0.81 pad 1.27)
  Top 0.406: v32.07,33.65 36.2,37.78 60.64,37.78 63.5,40.64 73.66,40.64 75.56,38.73 75.56,35.56 72.07,32.07 68.58,32.07 v66.67,30.16
  Bottom 0.406: v66.67,30.16 66.48,29.96 PIC18F46K22.26 | v32.07,33.65 30.12,33.65 U$3.CD 29.01,33.54 28.26,34.29 24.77,34.29 23.18,32.7 R9.1
N$19  (via drill 0.81 pad 1.27)
  Top 0.406: v40.64,24.45 51.12,34.93 68.26,34.93 v68.58,35.24
  Bottom 0.406: 40.7,21.65 U$3.5 40.64,22.27 v40.64,24.45 | PIC18F46K22.37 68.81,35.47 v68.58,35.24
N$20  (via drill 0.81 pad 1.27)
  Top 0.406: ICSP.1 41.28,18.1 42.55,19.37 v45.72,19.37
  Bottom 0.406: PIC18F46K22.18 69.61,17.54 68.58,16.51 58.74,16.51 54.93,20.32 46.67,20.32 v45.72,19.37
N$21
  Bottom 0.406: PIC18F46K22.27 62.58,30.76 51.44,41.91 30.68,41.91 U$3.WP 30,42.9 R4.1
N$22
  Bottom 0.406: PIC18F46K22.30 62.09,33.16 60.33,34.93 60.33,43.18 61.09,43.94 Q1.1 61.09,48.89 C8.1
N$23
  Bottom 0.406: DS1339C-33#.2 90.81,24.76 91.44,24.13 R5.1 92.71,24 IC1.11
N$24
  Bottom 0.406: PIC18F46K22.17 70.41,17.07 68.9,15.56 58.42,15.56 54.61,19.37 50.64,19.37 48.89,17.62 ICSP.4
N$25
  Bottom 0.305: U$4.2 123.83,47.94 122.56,46.67 122.56,35.24 123.51,34.29 123.51,29.53 SCL1.1 SCL2.1
N$26
  Bottom 0.406: PIC18F46K22.3 98.42,33.96 100.01,35.56 LCD9-16.4
N$27  (via drill 0.81 pad 1.27)
  Top 0.305: SDA2.1 SDA1.1 123.51,29.53 123.51,46.04 v123.83,46.35
  Bottom 0.305: U$4.1 124.46,50.19 124.46,46.99 v123.83,46.35
N$28  (via drill 0.81 pad 1.27)
  Top 0.305: v122.56,48.58 121.92,47.94 121.92,34.93 122.24,34.61 GND1.1 GND2.1
  Bottom 0.305: 121.92,50.16 121.92,53.98 122.51,54.56 U$4.5 U$4.6 | U$4.4 122.48,50.16 121.92,50.16 | 121.92,50.16 121.92,49.21 v122.56,48.58
N$29
  Bottom 0.406: LCD1-8.5 27.94,33.02 29.53,31.43 51.12,31.43 58.1,24.45 66.99,24.45 67.21,24.66 PIC18F46K22.21
N$30  (via drill 0.81 pad 1.27)
  Top 0.406: v67.95,49.21 23.81,49.21 22.86,48.26 12.7,48.26 11.43,46.99 11.43,26.51 X3.14
  Bottom 0.406: 68.01,40.32 68.01,49.15 v67.95,49.21 | 68.01,40.32 PIC18F46K22.36 | 68.01,40.32 R3.2
N$31
  Bottom 0.406: PIC18F46K22.14 72.81,12.92 75.56,10.16 RB3.3
N$32
  Bottom 0.406: PIC18F46K22.15 72.01,16.13 66.04,10.16 RB2.4 RB2.3
N$33
  Top 1.27: S2.6 S2.3 102.07,46.99 79.38,46.99 24.45,46.99 21.07,46.99 X3.1
N$34
  Top 0.406: LCD1-8.3 34.92,38.1 35.56,38.73 60.01,38.73 62.86,41.59 73.98,41.59 76.84,38.73 94.62,38.73 96.84,36.51 96.84,18.1 CONTRAST.S
N$35  (via drill 0.81 pad 1.27)
  Top 0.406: 19.26,39.05 17.15,39.05 15.88,37.78 15.88,14.29 14.92,13.34 13.97,13.34 13.34,12.7 JP5.1 | 19.26,39.05 X3.2 | 19.26,39.05 24.77,39.05 25.08,39.37 34.61,39.37 34.92,39.69 59.37,39.69 62.23,42.54 80.33,42.54 | 80.33,42.54 v80.33,40.64 | 80.33,42.54 v80.33,45.4
  Bottom 0.406: PIC18F46K22.39 70.41,39.29 71.75,40.64 v80.33,40.64 81.92,40.64 83.82,42.54 88.27,42.54 | U$5.5 13.02,10.48 JP5.1 | 24AA1025.5 79.69,46.04 v80.33,45.4 | DS1339C-33#.16 92.08,38.73 88.27,42.54 | R6.1 89.54,43.82 88.27,42.54
N$36  (via drill 0.81 pad 1.27)
  Top 0.406: v74.3,28.26 79.06,28.26 80.33,26.99 80.33,19.37 v82.55,17.15
  Bottom 0.406: v82.55,17.15 85.09,17.15 89.54,12.7 95.57,12.7 96.52,13.65 IC1.3 | PIC18F46K22.10 74.4,28.36 v74.3,28.26
N$37
  Top 1.27: 107.95,28.26 LM2574.7 | 107.95,28.26 107.97,26.01 D2.C | 107.95,28.26 107.95,38.71 L2.1
N$38
  Bottom 0.406: PIC18F46K22.5 98.13,32.36 100.01,30.48 LCD9-16.6
N$39
  Bottom 0.305: U$4.8 U$4.7 124.41,54.56 124.46,54.61 125.09,53.98 125.09,34.93 124.78,34.61 VDD1.1 VDD2.1
N$40
  Bottom 0.406: 134.62,19.68 134.62,29.21 133.98,29.84 133.98,55.88 129.54,55.88 129.54,29.84 128.91,29.21 128.91,19.68 134.62,19.68
N$41
  Bottom 0.406: 120.65,0.63 150.18,0.63 150.18,17.15 120.65,17.15 120.65,0.63
N$42
  Bottom 0.406: PIC18F46K22.31 62.56,33.96 61.59,34.93 61.59,40.13 Q1.2 65.91,48.89 C10.1
N$43
  Bottom 0.406: 120.65,19.68 126.37,19.68 126.37,34.29 125.73,34.93 125.73,55.88 121.29,55.88 121.29,34.93 120.65,34.29 120.65,19.68
N$44
  Top 0.406: JP1.2 27.94,17.46 22.23,23.18 22.23,31.43 21.08,32.58 X3.4
N$45
  Bottom 0.406: MMBT3904.B 25.08,15.55 26.04,16.51 27.49,16.51 R12.1
N$46
  Bottom 0.305: U$6.6 U$6.7 U$6.8 133.35,53.95 133.35,29.84 133.03,29.53 VDD3.1
N$47  (via drill 0.81 pad 1.27)
  Top 0.406: v30.48,24.45 42.86,36.83 62.55,36.83 v62.86,37.15
  Bottom 0.406: PIC18F46K22.32 63.34,34.76 62.86,35.24 v62.86,37.15 | JP1.3 25.4,12.7 23.18,14.92 MMBT3904.E 22.86,15.41 22.86,18.41 24.13,19.68 R11.2 28.13,22.09 v30.48,24.45
N$48  (via drill 0.81 pad 1.27)
  Top 0.305: v130.81,48.58 130.18,47.94 130.18,29.84 130.49,29.53 GND3.1
  Bottom 0.305: U$6.5 130.18,53.95 130.18,50.16 | U$6.4 130.74,50.16 130.18,50.16 | 130.18,50.16 130.18,49.21 v130.81,48.58
N$49  (via drill 0.81 pad 1.27)
  Top 0.305: v132.08,46.35 131.76,46.04 131.76,26.99 SDA3.1
  Bottom 0.305: U$6.1 132.74,47.01 v132.08,46.35
N$50
  Bottom 0.305: U$6.2 132.09,47.95 130.81,46.67 130.81,30.16 131.76,29.21 131.76,26.99 SCL3.1
N$51
  Bottom 0.406: 137.16,55.88 142.24,55.88 142.24,19.68 137.16,19.68 137.16,55.88
N$52
  Top 0.406: R16.1 137.66,12.06 C5.1 134.75,9.71 IC3.7 IC3.6
N$53
  Bottom 0.406: R12.2 R10.1 30.48,13.2 JP1.1
N$54
  Bottom 0.406: ILS-IN2.1 138.43,47.62 ILS-IN3.1 ILS-IN5.1
N$55
  Bottom 0.406: ILS-IN1.1 146.05,47.62 ILS-IN4.1 ILS-IN6.1
N$56
  Bottom 0.406: ILS-OUT1.1 148.59,29.84 ILS-OUT6.1 ILS-OUT4.1
N$57
  Bottom 0.406: ILS-OUT2.1 140.97,29.84 ILS-OUT5.1 ILS-OUT3.1
N$58
  Top 0.406: IC3.3 135.89,5.71 136.21,6.03 137.79,6.03 138.11,5.71 143.9,5.71 X2.1
N$59  (via drill 0.81 pad 1.27)
  Top 0.406: v134.62,6.67 IC3.2 | R15.1 130.31,14.6 C6.2 129.99,13.46 129.37,12.85 T1.3 127.15,12.85 125.73,11.43 v125.73,6.67
  Bottom 0.406: v125.73,6.67 v134.62,6.67
N$60  (1 unrouted)
  Top 1.27: C3.2 122.87,2.22 122.87,12.38
  Bottom 1.27: 122.87,2.22 PAD1.1
N$61  (via drill 0.81 pad 1.27)
  Top 0.406: 137.66,14.6 R16.2 | 137.66,14.6 R15.2 133.35,13.2 IC3.8 | 137.66,14.6 139.57,14.6 C4.2 144.89,14.73 X2.3 | IC3.4 137.42,4.13 v138.75,4.13
  Bottom 0.406: v138.75,4.13 141.92,4.13 144.15,1.91 147.32,1.91 148.59,3.17 148.59,12.06 146.69,13.97 145.81,13.97 X2.3
N$62
  Top 0.305: DIS2.7 161.61,35.11 R7.1
N$63
  Bottom 0.406: 144.78,19.68 144.78,55.88 149.86,55.88 149.86,19.68 144.78,19.68
N$64
  Top 0.305: DIS2.6 164.15,35.75 R13.1
N$65
  Top 0.305: DIS2.4 161.61,17.15 161.29,16.83 R17.1
N$66  (via drill 0.81 pad 1.27)
  Top 0.305: R7.2 160.66,39.69 v161.61,40.64 | U$2.14 154.99,6.62 v154.94,6.67
  Bottom 0.305: v161.61,40.64 160.34,39.37 160.34,12.06 v154.94,6.67
N$67
  Top 0.305: DIS2.1 153.99,17.15 154.31,16.83 R19.1
N$68
  Top 0.305: DIS2.9 156.53,35.11 R20.1
N$69
  Top 0.305: DIS2.10 153.99,35.75 R21.1
N$70
  Bottom 0.406: U$5.4 11.11,11.75 11.75,12.38 11.75,15.24 12.29,15.78 X3.16
N$71
  Top 0.305: 159.07,20.64 DIS2.3 | 159.07,20.64 159.07,31.43 | 159.07,31.43 DIS2.8 | 159.07,31.43 161.93,31.43 162.88,32.38 162.88,34.61 162.24,35.24 162.24,39.69 162.88,40.32 JP2.4 | U$2.4 163.83,8.57 | 163.83,8.57 164.78,9.52 164.78,15.56 162.88,17.46 162.88,19.68 161.93,20.64 159.07,20.64 | U$2.1 163.47,6.62 163.83,6.98 163.83,8.57
N$72  (via drill 0.81 pad 1.27)
  Top 0.305: R13.2 163.83,40.32 v164.15,40.64 | U$2.13 158.72,7.27 160.66,9.21 v160.66,9.84
  Bottom 0.305: v164.15,40.64 162.88,39.37 162.88,12.06 v160.66,9.84
N$73
  Top 0.305: U$2.12 158.42,7.92 159.07,8.57 159.07,10.79 159.7,11.43 160.66,11.43 R17.2
N$74
  Top 0.305: R18.2 156.84,12.06 158.12,10.79 158.12,9.21 157.48,8.57 U$2.11
N$75
  Top 0.305: R19.2 154.31,12.38 153.35,11.43 153.35,8.89 153.99,8.25 154.94,8.25 155.91,9.22 U$2.10
N$76  (via drill 0.81 pad 1.27)
  Top 0.305: R20.2 157.48,39.69 v156.53,40.64 | U$2.9 154.97,9.87 v154.62,9.52
  Bottom 0.305: v156.53,40.64 157.8,39.37 157.8,12.7 v154.62,9.52
N$77  (via drill 0.81 pad 1.27)
  Top 0.305: R21.2 154.31,40.32 v153.99,40.64 | U$2.8 155.53,10.52 154.94,11.11 v154.62,11.11
  Bottom 0.305: v153.99,40.64 155.26,39.37 155.26,17.15 154.62,16.51 v154.62,11.11
N$78
  Top 0.305: DIS2.2 156.53,17.15 156.84,16.83 R18.1
N$79
  Top 0.305: 162.56,9.21 162.58,9.22 U$2.5 162.63,9.21 163.51,9.21 164.15,9.84 164.15,13.34 163.19,14.29 159.7,14.29 159.07,14.92 159.07,16.19 157.8,17.46 157.8,19.68 155.26,22.23 155.26,34.61 155.89,35.24 155.89,39.69 155.26,40.32 JP2.1
N$80
  Top 0.305: U$2.3 160.32,7.92 159.7,7.3 159.7,5.71 159.07,5.08 155.89,5.08 155.26,4.45 JP3.1
N$81
  Top 0.305: U$2.2 161.9,7.27 161.29,6.67 161.29,6.35 162.88,4.76 JP3.4
N$82  (via drill 0.81 pad 1.27)
  Top 0.406: v6.67,9.84 6.67,7.94 7.94,6.67 19.69,6.67 22.54,9.52 22.54,14.29 21.05,15.78 X3.8
  Bottom 0.406: U$5.3 7.94,13.02 6.67,11.75 v6.67,9.84
VDD  (via drill 0.81 pad 1.27)
  Top 1.27: L2.2 114.33,36.85 111.76,34.29 111.76,27.62 LM2574.1 115.89,23.49 115.89,14.29 113.98,12.38 108.64,12.38 C11.+ 106.05,14.97 v106.05,18.41
  Bottom 0.406: PIC18F46K22.28 69.4,31.56 70.2,30.76 PIC18F46K22.7 77.69,30.76 C2.2 | 32.7,7.62 32.7,12.38 | 32.7,12.38 32.7,17.15 31.75,18.1 24.94,18.1 MMBT3904.C | 32.7,12.38 43.18,12.38 43.81,13.02 ICSP.2 43.81,18.73 43.2,19.35 U$3.4 | LCD1-8.2 23.81,40.64 21.27,43.18 16.51,43.18 | 16.51,24.18 16.51,32.58 | 16.51,40.98 16.51,43.18 | 16.51,43.18 16.51,47.31 17.46,48.26 20.96,48.26 | 24AA1025.3 24AA1025.2 24AA1025.1 24AA1025.8 78.74,42.23 79.38,42.86 82.23,42.86 85.41,46.04 96.52,46.04 | U$5.2 U$5.1 9.74,17.78 | 20.96,48.26 22.86,48.26 23.81,49.21 26.22,49.21 R4.2 | 20.96,48.26 JP4.4 | 16.51,40.98 X3.10 | 16.51,32.58 X3.12 | 16.51,32.58 16.51,40.98 | 16.51,24.18 X3.6 21.64,24.18 23.18,25.72 R9.2 | 16.51,19.98 16.51,24.18 | 16.51,19.98 X3.15 11.56,17.78 9.74,17.78 | C7.2 9.74,17.78 | 16.51,19.98 16.51,14.6 17.46,13.65 21.59,13.65 22.86,12.38 22.86,8.89 24.13,7.62 32.7,7.62 | R8.2 R6.2 96.65,45.91 96.52,46.04 | 32.7,7.62 82.87,7.62 | CONTRAST.A 91.12,6.03 89.54,7.62 82.87,7.62 | 82.87,7.62 82.87,12.38 80.33,14.92 80.33,27.94 82.23,29.84 89.54,29.84 | 96.52,46.04 102.55,46.04 104.46,44.13 104.46,28.89 103.51,27.94 LCD9-16.7 95.25,27.94 | 89.54,29.84 DS1339C-33#.3 | 89.54,29.84 93.34,29.84 95.25,27.94 | 95.25,27.94 95.38,27.81 R5.2 98.11,24.13 99.06,23.18 IC1.16 99.06,19.37 100.01,18.41 v106.05,18.41
  Bottom 1.27: 80.33,27.94 C2.2
VSS  (via drill 0.81 pad 1.27)
  Top 1.27: C13.- 111.28,43.34 109.86,41.91 v109.86,29.53 109.86,24.11 D2.A 112.34,21.56 C11.-
  pour Bottom: 1.27,55.24 117.48,55.24 117.48,1.27 1.27,1.27
VSS2
  Top 0.406: D1.A 130.18,8.57 129.54,9.21 T1.2 | C6.1 127.19,15.74 127.95,16.51 130.81,16.51
  pour Top: 130.81,2.86 130.81,16.51 147.95,16.51 149.54,14.92 149.54,2.86 147.95,1.27 132.4,1.27

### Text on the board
Top: Picfano v0.5/Edouard Pigeon
Bottom: 9.GND | 1.VDD | 11.GND | 10.VDD | 3.SCL | 2.SDA | 13.GND | 12.VDD | 5.NC | 4.RPM | 8/16.TH-K | 7/15.ILS | 6/14.SPEED | VDD | RPM IN | GND | RPM OUT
